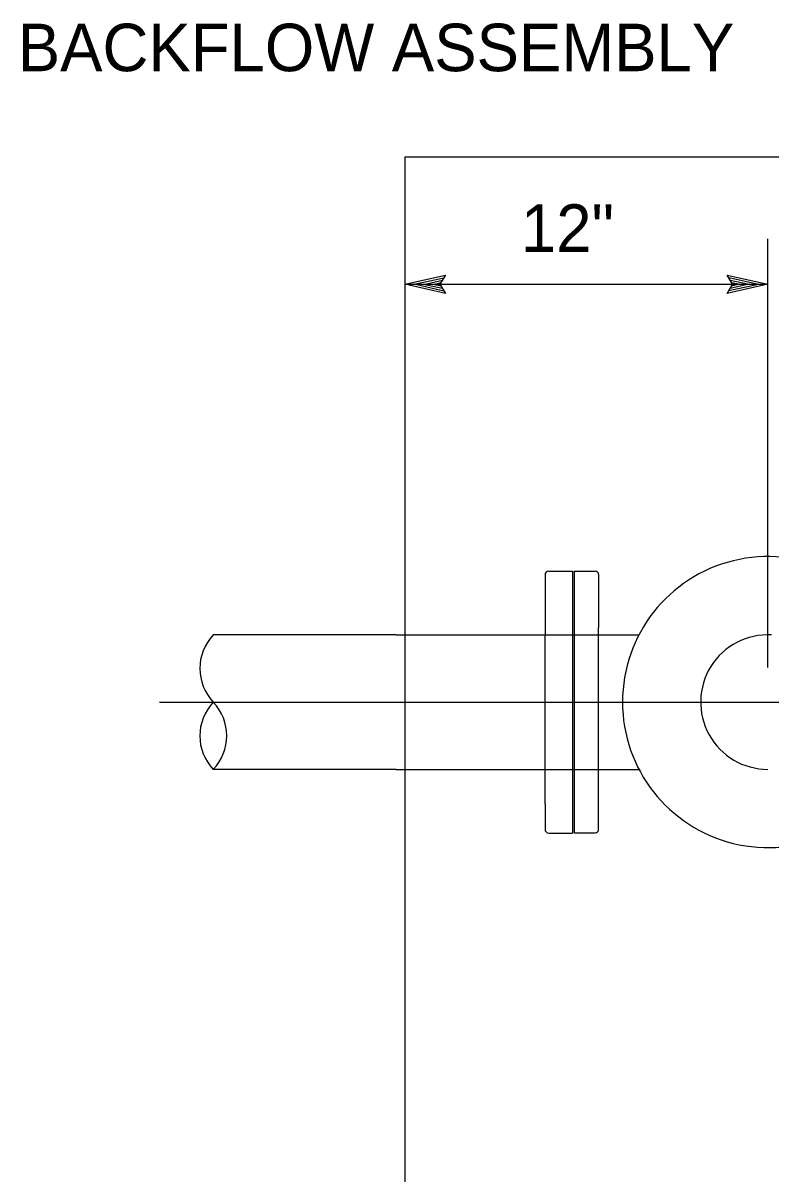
# Model space of a CAD drawing. Extents: x 6710407 to 6714861, y 1868090 to 1871317.
# Drawn here: x 6713604.4 to 6713714.5, y 1869994.1 to 1870163.5 of the extents above; entities that cross this region are included whole.
import ezdxf

# ---------------------------------------------------------------- set-up
doc = ezdxf.new("R2010")
doc.units = 0
doc.layers.add('Nongeo Data(60)', color=7, linetype='Continuous')

msp = doc.modelspace()

# ---------------------------------------------------------------- linework, layer by layer
at = {"layer": 'Nongeo Data(60)'}
for p, q in [((6713660.63, 1870143.75), (6713660.63, 1869916.69)), ((6713660.63, 1870143.75), (6714082.91, 1870143.75)), ((6713714.16, 1870068.54), (6713714.16, 1870131.68)), ((6713660.63, 1870124.97), (6713666.63, 1870126.3)), ((6713662.03, 1870124.97), (6713666.4, 1870125.94)), ((6713666.63, 1870126.3), (6713665.83, 1870124.97)), ((6713666.63, 1870126.3), (6713666.63, 1870126.3)), ((6713708.96, 1870124.97), (6713708.16, 1870126.31)), ((6713708.16, 1870126.31), (6713708.16, 1870126.31)), ((6713708.16, 1870126.31), (6713714.16, 1870124.97)), ((6713708.38, 1870125.95), (6713712.78, 1870124.97)), ((6713666.63, 1870123.63), (6713660.63, 1870124.97)), ((6713660.63, 1870124.97), (6713660.63, 1870124.97)), ((6713660.63, 1870124.97), (6713714.16, 1870124.97)), ((6713666.42, 1870123.98), (6713662.01, 1870124.97)), ((6713663.4, 1870124.96), (6713666.22, 1870125.59)), ((6713666.18, 1870124.34), (6713663.4, 1870124.96)), ((6713664.78, 1870124.96), (6713665.99, 1870125.23)), ((6713666.01, 1870124.69), (6713664.78, 1870124.96)), ((6713665.83, 1870124.97), (6713666.63, 1870123.63)), ((6713714.16, 1870124.97), (6713708.16, 1870123.64)), ((6713708.16, 1870123.64), (6713708.96, 1870124.97)), ((6713712.77, 1870124.96), (6713708.4, 1870124)), ((6713711.4, 1870124.97), (6713708.58, 1870124.34)), ((6713708.61, 1870125.59), (6713711.4, 1870124.97)), ((6713708.79, 1870125.24), (6713710.02, 1870124.97)), ((6713710.02, 1870124.97), (6713708.81, 1870124.7)), ((6713714.16, 1870124.97), (6713714.16, 1870124.97)), ((6713666.63, 1870123.63), (6713666.63, 1870123.63)), ((6713708.16, 1870123.64), (6713708.16, 1870123.64)), ((6713681.32, 1870082.16), (6713681.32, 1870073.38)), ((6713681.87, 1870082.72), (6713685.35, 1870082.72)), ((6713685.35, 1870082.72), (6713685.35, 1870054.09)), ((6713685.62, 1870082.71), (6713685.62, 1870054.67)), ((6713685.62, 1870082.71), (6713688.7, 1870082.71)), ((6713689.22, 1870082.2), (6713689.22, 1870074.4)), ((6713659.38, 1870073.33), (6713632.41, 1870073.33)), ((6713659.38, 1870073.33), (6713695.16, 1870073.33)), ((6713681.32, 1870048.38), (6713681.32, 1870073.38)), ((6713689.22, 1870052.43), (6713689.22, 1870074.4)), ((6713624.49, 1870063.43), (6714119.34, 1870063.43)), ((6713685.62, 1870054.67), (6713685.62, 1870044.15)), ((6713659.38, 1870053.51), (6713632.41, 1870053.51)), ((6713659.38, 1870053.51), (6713695.17, 1870053.51)), ((6713685.35, 1870054.09), (6713685.35, 1870044.14)), ((6713689.22, 1870044.67), (6713689.22, 1870052.46)), ((6713681.32, 1870048.38), (6713681.32, 1870044.7)), ((6713681.87, 1870044.14), (6713685.35, 1870044.14)), ((6713685.62, 1870044.15), (6713688.7, 1870044.15))]:
    msp.add_line(p, q, dxfattribs=at)
for centre, radius, start, end in [((6713714.16, 1870063.43), 21.43, 27.5041, 332.4289), ((6713681.87, 1870082.16), 0.557, 90, 180), ((6713688.7, 1870082.2), 0.514, 0, 90), ((6713637.64, 1870068.38), 7.2, 136.5226, 223.5571), ((6713714.16, 1870063.43), 9.91, 86.9128, 269.9994), ((6713637.64, 1870058.45), 7.2, 136.461, 223.4594), ((6713627.21, 1870058.46), 7.19, 316.3237, 43.5967), ((6713681.87, 1870044.7), 0.557, 180, 270), ((6713688.7, 1870044.67), 0.514, 270, 0)]:
    msp.add_arc(centre, radius, start, end, dxfattribs=at)

# ---------------------------------------------------------------- texts
for s, p in [('BACKFLOW ASSEMBLY', (6713603.61, 1870156.36)), ('12"', (6713677.76, 1870129.75))]:
    msp.add_text(s, height=7, dxfattribs=at).set_placement(p)

doc.saveas('drawing.dxf')
